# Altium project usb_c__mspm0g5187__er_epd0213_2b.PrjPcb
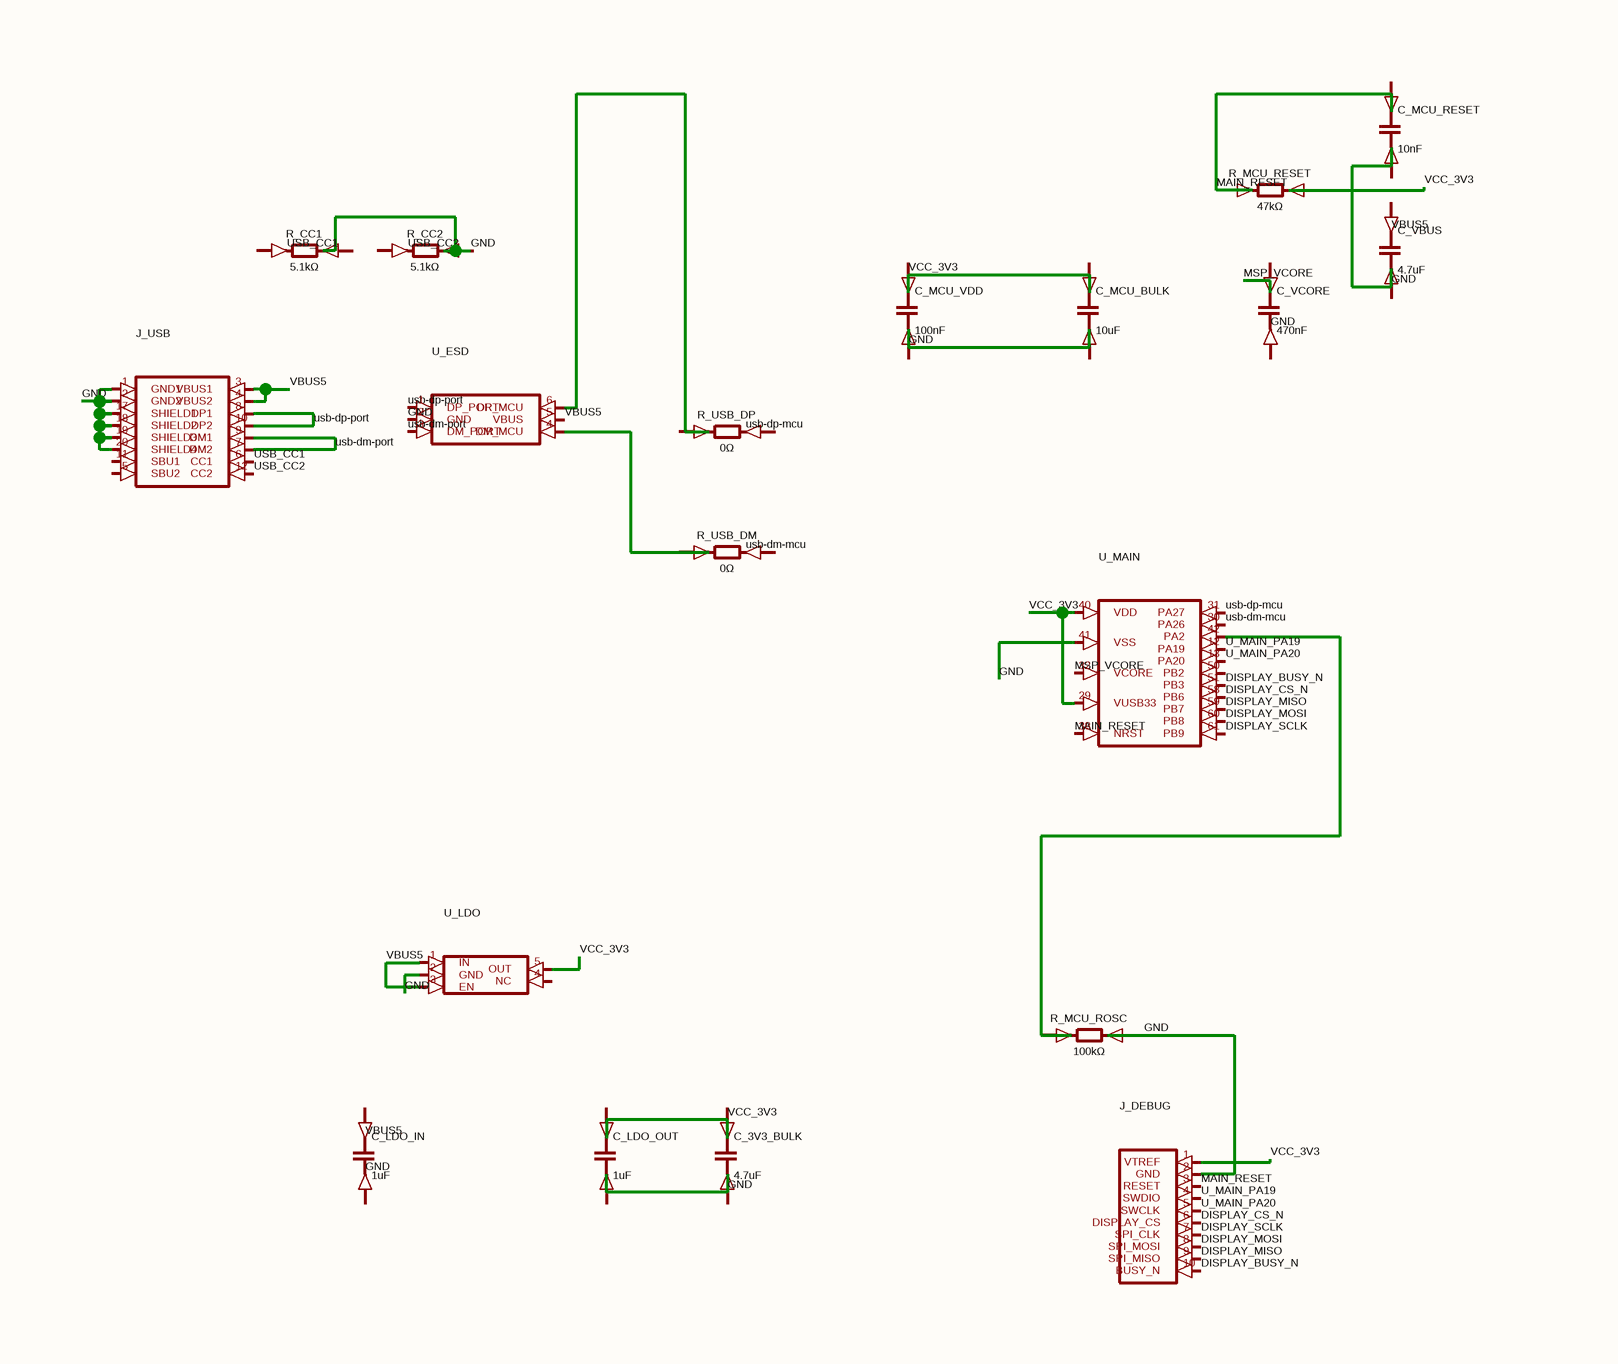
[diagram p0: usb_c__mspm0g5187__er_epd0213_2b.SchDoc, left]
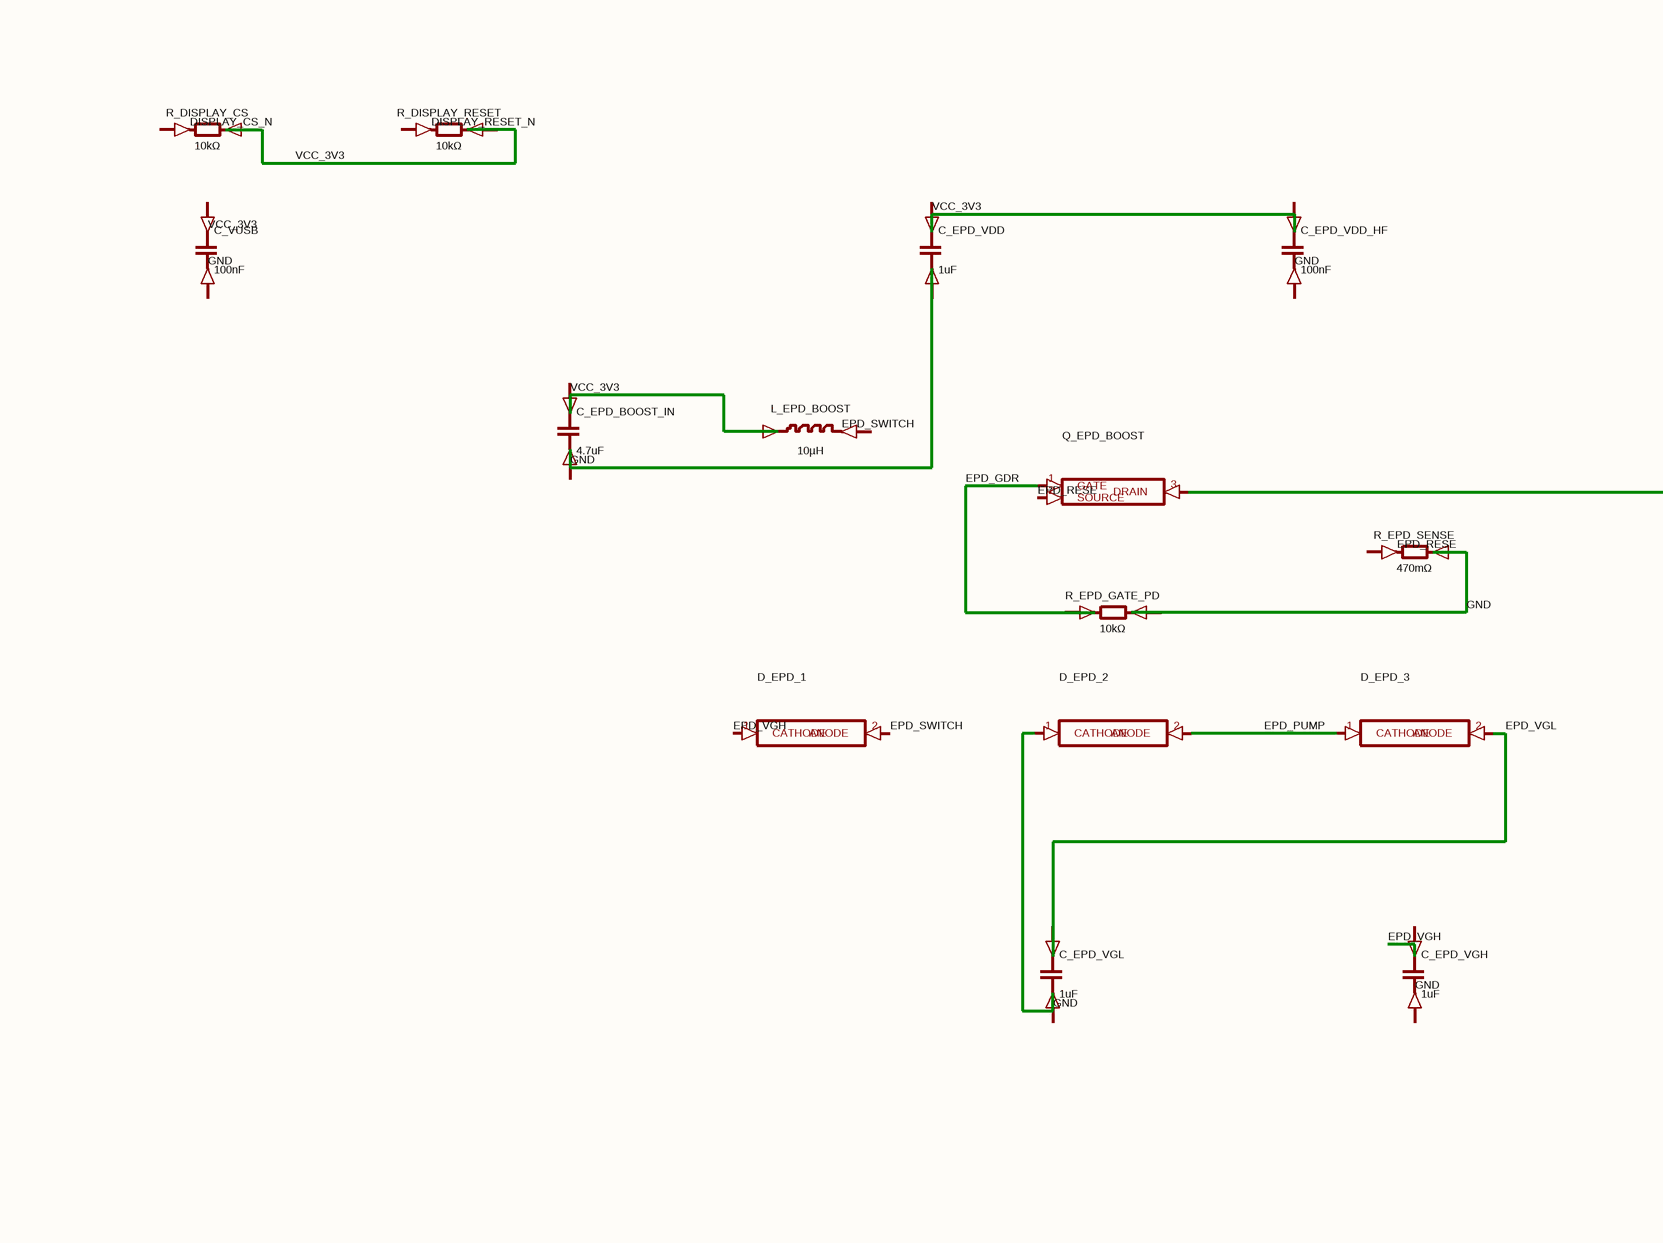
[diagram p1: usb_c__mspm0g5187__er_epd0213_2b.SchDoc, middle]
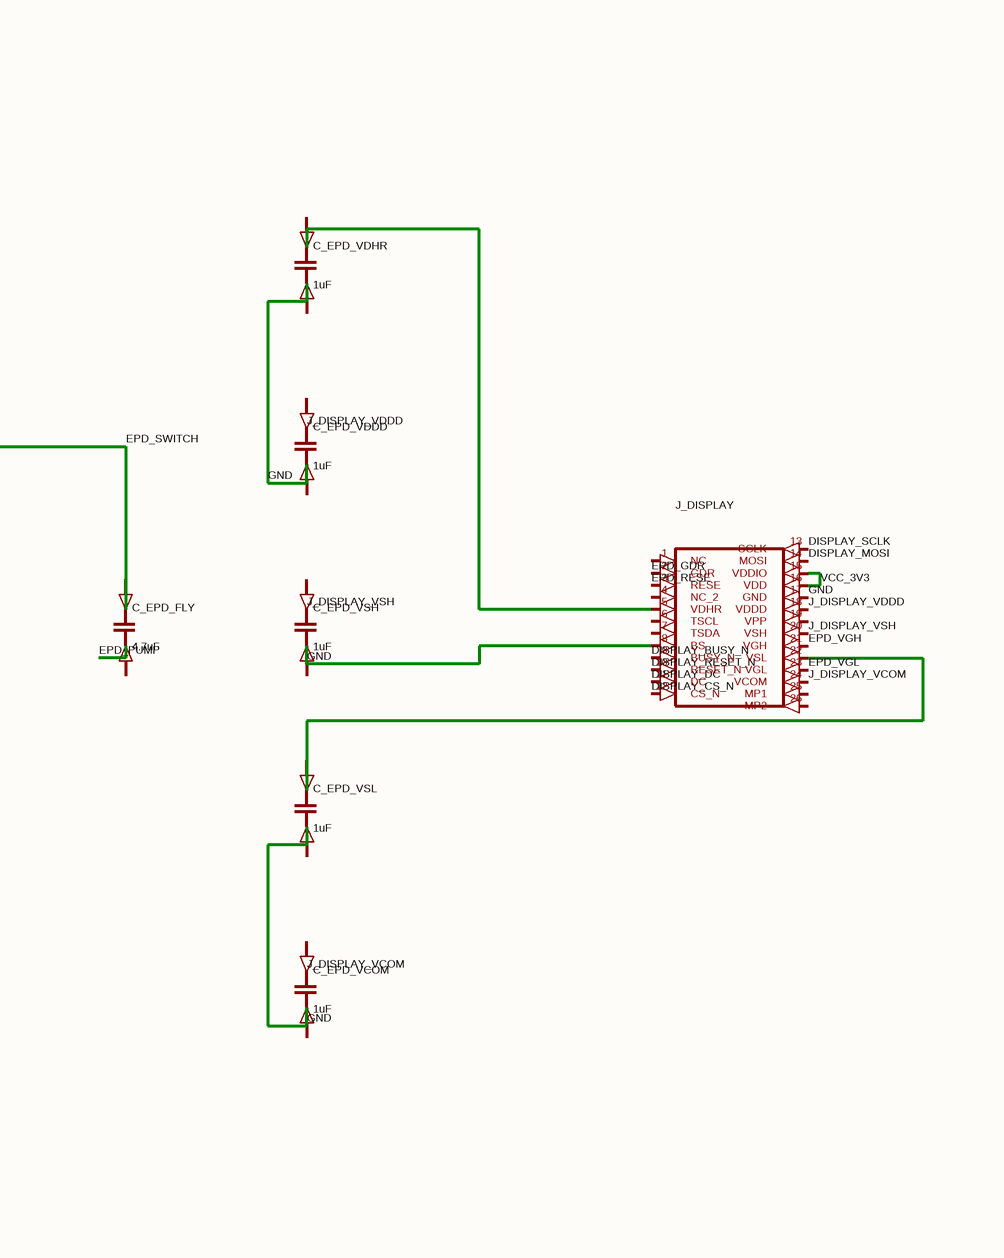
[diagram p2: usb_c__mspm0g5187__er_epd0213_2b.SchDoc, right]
1 sheet, 41 parts. Net scope: global (net labels, ports and power ports of the same name join across sheets).
Board file: usb_c__mspm0g5187__er_epd0213_2b.PcbDoc

## Sheet usb_c__mspm0g5187__er_epd0213_2b.SchDoc
size 385 x 149 mm

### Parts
C_3V3_BULK  4.7uF
C_EPD_BOOST_IN  4.7uF
C_EPD_FLY  4.7uF
C_EPD_VCOM  1uF
C_EPD_VDD  1uF
C_EPD_VDD_HF  100nF
C_EPD_VDDD  1uF
C_EPD_VDHR  1uF
C_EPD_VGH  1uF
C_EPD_VGL  1uF
C_EPD_VSH  1uF
C_EPD_VSL  1uF
C_LDO_IN  1uF
C_LDO_OUT  1uF
C_MCU_BULK  10uF
C_MCU_RESET  10nF
C_MCU_VDD  100nF
C_VBUS  4.7uF
C_VCORE  470nF
C_VUSB  100nF
D_EPD_1  (no value)
D_EPD_2  (no value)
D_EPD_3  (no value)
J_DEBUG  (no value)
J_DISPLAY  (no value)
J_USB  (no value)
L_EPD_BOOST  10µH
Q_EPD_BOOST  (no value)
R_CC1  5.1kΩ
R_CC2  5.1kΩ
R_DISPLAY_CS  10kΩ
R_DISPLAY_RESET  10kΩ
R_EPD_GATE_PD  10kΩ
R_EPD_SENSE  470mΩ
R_MCU_RESET  47kΩ
R_MCU_ROSC  100kΩ
R_USB_DM  0Ω
R_USB_DP  0Ω
U_ESD  (no value)
U_LDO  (no value)
U_MAIN  (no value)

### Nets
DISPLAY_BUSY_N: J_DEBUG.10(BUSY_N) J_DISPLAY.9(BUSY_N) U_MAIN.51(PB3)
DISPLAY_CS_N: J_DEBUG.6(DISPLAY_CS) J_DISPLAY.12(CS_N) U_MAIN.58(PB6)
DISPLAY_DC: J_DISPLAY.11(DC)
DISPLAY_MISO: J_DEBUG.9(SPI_MISO) U_MAIN.59(PB7)
DISPLAY_MOSI: J_DEBUG.8(SPI_MOSI) J_DISPLAY.14(MOSI) U_MAIN.60(PB8)
DISPLAY_RESET_N: J_DISPLAY.10(RESET_N)
DISPLAY_SCLK: J_DEBUG.7(SPI_CLK) J_DISPLAY.13(SCLK) U_MAIN.61(PB9)
EPD_GDR: J_DISPLAY.2(GDR) Q_EPD_BOOST.1(GATE) R_EPD_GATE_PD.1(anode)
EPD_PUMP: D_EPD_2.2(ANODE) D_EPD_3.1(CATHODE)
EPD_RESE: J_DISPLAY.3(RESE) Q_EPD_BOOST.2(SOURCE)
EPD_SWITCH: C_EPD_FLY.1(anode) D_EPD_1.2(ANODE) Q_EPD_BOOST.3(DRAIN)
EPD_VGH: D_EPD_1.1(CATHODE) J_DISPLAY.21(VGH)
EPD_VGL: C_EPD_VGL.1(anode) D_EPD_3.2(ANODE) J_DISPLAY.23(VGL)
GND: C_EPD_VDD.2(cathode) D_EPD_2.1(CATHODE) J_DEBUG.1(VTREF) J_DEBUG.2(GND) J_DISPLAY.8(BS) J_DISPLAY.15(VDDIO) J_DISPLAY.16(VDD) J_DISPLAY.17(GND) J_USB.1(GND1) J_USB.2(GND2) J_USB.3(VBUS1) J_USB.4(VBUS2) J_USB.17(SHIELD1) J_USB.18(SHIELD2) J_USB.19(SHIELD3) J_USB.20(SHIELD4) L_EPD_BOOST.1(anode) R_DISPLAY_CS.2(cathode) R_DISPLAY_RESET.2(cathode) R_EPD_GATE_PD.2(cathode) R_EPD_SENSE.2(cathode) R_MCU_RESET.2(cathode) R_MCU_ROSC.2(cathode) U_ESD.2(GND) U_ESD.5(VBUS) U_LDO.1(IN) U_LDO.2(GND) U_LDO.3(EN) U_LDO.5(OUT) U_MAIN.29(VUSB33) U_MAIN.40(VDD) U_MAIN.41(VSS)  [also labelled VBUS5, VCC_3V3]
J_DISPLAY_VCOM: J_DISPLAY.24(VCOM)
J_DISPLAY_VDDD: J_DISPLAY.18(VDDD)
J_DISPLAY_VSH: J_DISPLAY.20(VSH)
MAIN_RESET: J_DEBUG.3(RESET) R_MCU_RESET.1(anode) U_MAIN.38(NRST)
MSP_VCORE: U_MAIN.32(VCORE)
U_MAIN_PA19: J_DEBUG.4(SWDIO) U_MAIN.12(PA19)
U_MAIN_PA20: J_DEBUG.5(SWCLK) U_MAIN.13(PA20)
usb-dm-mcu: U_MAIN.30(PA26)
usb-dm-port: J_USB.7(DM2) J_USB.9(DM1) U_ESD.3(DM_PORT)
usb-dp-mcu: U_MAIN.31(PA27)
usb-dp-port: J_USB.8(DP1) J_USB.10(DP2) U_ESD.1(DP_PORT)
USB_CC1: J_USB.6(CC1)
USB_CC2: J_USB.12(CC2)
NetC_EPD_VSL_1: C_EPD_VSL.1(anode) J_DISPLAY.22(VSL)
NetR_MCU_ROSC_1: R_MCU_ROSC.1(anode) U_MAIN.42(PA2)
NetR_USB_DM_1: R_USB_DM.1(anode) U_ESD.4(DM_MCU)

Not connected (* = marked no-connect by the designer): C_3V3_BULK 1(anode) 2(cathode); C_EPD_BOOST_IN 1(anode) 2(cathode); C_EPD_FLY 2(cathode); C_EPD_VCOM 1(anode) 2(cathode); C_EPD_VDD 1(anode); C_EPD_VDD_HF 1(anode) 2(cathode); C_EPD_VDDD 1(anode) 2(cathode); C_EPD_VDHR 1(anode) 2(cathode); C_EPD_VGH 1(anode) 2(cathode); C_EPD_VGL 2(cathode); C_EPD_VSH 1(anode) 2(cathode); C_EPD_VSL 2(cathode); C_LDO_IN 1(anode) 2(cathode); C_LDO_OUT 1(anode) 2(cathode); C_MCU_BULK 1(anode) 2(cathode); C_MCU_RESET 1(anode) 2(cathode); C_MCU_VDD 1(anode) 2(cathode); C_VBUS 1(anode) 2(cathode); C_VCORE 1(anode) 2(cathode); C_VUSB 1(anode) 2(cathode); J_DISPLAY 1(NC) 4(NC_2) 5(VDHR) 6(TSCL) 7(TSDA) 19(VPP) 25(MP1) 26(MP2); J_USB 5(SBU2) 11(SBU1); L_EPD_BOOST 2(cathode); R_CC1 1(anode) 2(cathode); R_CC2 1(anode) 2(cathode); R_DISPLAY_CS 1(anode); R_DISPLAY_RESET 1(anode); R_EPD_SENSE 1(anode); R_USB_DM 2(cathode); R_USB_DP 1(anode) 2(cathode); U_ESD 6(DP_MCU); U_LDO 4(NC); U_MAIN 50(PB2)

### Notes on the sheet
- Labels drawn without touching a wire or pin: DISPLAY_CS_N, DISPLAY_RESET_N, EPD_RESE, EPD_SWITCH, GND, J_DISPLAY_VCOM, J_DISPLAY_VDDD, J_DISPLAY_VSH, usb-dm-mcu, usb-dp-mcu, USB_CC1, USB_CC2, VBUS5, VCC_3V3

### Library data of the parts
C_3V3_BULK C_EPD_BOOST_IN C_EPD_FLY C_EPD_VCOM C_EPD_VDD C_EPD_VDD_HF C_EPD_VDDD C_EPD_VDHR C_EPD_VGH C_EPD_VGL C_EPD_VSH C_EPD_VSL C_LDO_IN C_LDO_OUT C_MCU_BULK C_MCU_RESET C_MCU_VDD C_VBUS C_VCORE C_VUSB = capacitor_down
D_EPD_1 = D_EPD_1
D_EPD_2 = D_EPD_2
D_EPD_3 = D_EPD_3
J_DEBUG = J_DEBUG
J_DISPLAY = J_DISPLAY
J_USB = J_USB
L_EPD_BOOST = inductor_right
Q_EPD_BOOST = Q_EPD_BOOST
R_CC1 R_CC2 R_DISPLAY_CS R_DISPLAY_RESET R_EPD_GATE_PD R_EPD_SENSE R_MCU_RESET R_MCU_ROSC R_USB_DM R_USB_DP = boxresistor_right
U_ESD = U_ESD
U_LDO = U_LDO
U_MAIN = U_MAIN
